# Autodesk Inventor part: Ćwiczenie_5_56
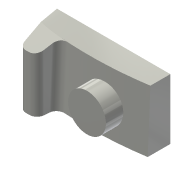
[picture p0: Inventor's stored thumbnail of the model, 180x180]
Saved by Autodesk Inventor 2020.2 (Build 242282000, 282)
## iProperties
Created: 2005-05
Part Number: Ćwiczenie_5_56
Document SubType Name: Modeling
Designer: F.Stasiak
Manufacturer: Standard
Standards Organization: Custom
Density: 1 g/cm^3
Material: Ogólny
Appearance: Gładkie — w kolorze kości słoniowej
Manager: www.cadconsulting.pl
Company: Fabian Stasiak CAD Consulting
Author: F.Stasiak
Subject: Zbiór ćwiczeń. Autodesk Inventor 2020. Kurs podstawowy
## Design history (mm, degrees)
sketch "Szkic1"
  geometry: L1 (-75, 0)-(75, 0); L2 (75, 0)-(75, -30); L3 (-75, 0)-(-75, -30); A1 r 496.531 centre (0, 460.834) between (-75, -30) and (75, -30); 2 further points
  constraints: 6 end point, 2 parallel, 2 point on circle, 1 centre point, 1 coincident, 1 horizontal, 1 midpoint, 1 perpendicular
  dimensions: "d0" = 150 distance of L1.start L1.end; "d1" = 30 distance of L1.end L2.end
extrude "Wyciągnięcie proste1" new body sketch "Szkic1" distance "d2" = 80; taper "d3" = 0 deg
feature "Szkic powierzchni1" dims angle "d4" = 2.5 deg
node "Płaszczyzna konstrukcyjna1"
sketch "Szkic6"
  geometry: C1 r 25 at (-19.767, 35.769)
  constraints: 1 centre point
  dimensions: "d14" = 50 diameter of C1
extrude "Wyciągnięcie proste3" join sketch "Szkic6" distance "d15" = 55; taper "d16" = 0 deg
sketch "Szkic14"
  geometry: L1 (0, 0)-(0, -80) reference; L2 (0, 0)-(35, 0); L3 (35, 0)-(35, -80); L4 (35, -80)-(0, -80); L5 (0, -80)-(0, 0)
  constraints: 8 end point, 2 parallel, 1 horizontal, 1 perpendicular
  dimensions: "d67" = 35 distance of L1.start L2.end
extrude "Wyciągnięcie proste4" join sketch "Szkic14" distance "d68" = 60; taper "d69" = 0 deg
sketch "Szkic16"
  geometry: L1 (80, 0)-(80, -60) reference; L2 (0, 0)-(80, 0) reference; L3 (0, 0)-(0, -60) reference; L4 (0, -60)-(80, -60) reference
extrude "Wyciągnięcie proste5" join sketch "Szkic16" distance "d85" = 9; taper "d86" = 0 deg
sketch "Szkic18"
  geometry: L1 (80, -60)-(0, -60) reference; L2 (80, 0)-(80, -60) reference; L3 (0, 0)-(80, 0) reference; L4 (0, -60)-(0, 0) reference
extrude "Wyciągnięcie proste6" cut sketch "Szkic18" distance "d116" = 9; taper "d117" = 0 deg
feature "Szkic powierzchni6" dims angle "d118" = 10 deg
feature "Szkic powierzchni7" dims angle "d119" = 5 deg
fillet "Zaokrąglenie2" dims "d120" = 10
sketch "Szkic20"
  geometry: L1 (-75, 0)-(-65.877, -51.736) reference; A1 r 493.038 centre (0, 460.834) between (-40, -30.579) and (75, -26.466) reference; A2 r 213.137 centre (-22.708, 181.855) between (-70.439, -25.868) and (-40, -30.579)
  constraints: 2 point on circle, 1 centre point, 1 midpoint, 1 tangent
feature "Podział8" sketch "Szkic20"
feature "Szkic powierzchni8" dims angle "d144" = 15 deg
fillet "Zaokrąglenie9" dims "d147" = 10
node "Płaszczyzna konstrukcyjna4"
node "Płaszczyzna konstrukcyjna5"
sketch "Szkic9"
  geometry: L1 (-75, 0)-(75, 0) reference; L2 (-40.884, -67.84)-(-37.231, -24.871); L3 (69.517, -25)-(80.483, -25); A1 r 16 centre (-55, -45) between (-70.121, -50.229) and (-39.057, -46.355); A2 r 182.693 centre (102.54, 9.477) between (-80, 2) and (-70.121, -50.229); A3 r 13.125 centre (75, -38.125) between (80.059, -26.014) and (69.941, -26.014); 7 further points
  constraints: 5 point on circle, 4 end point, 4 midpoint, 3 centre point, 2 horizontal, 2 tangent, 12 other
  dimensions: "d52" = 16 radius of A1; "d53" = 45 distance from line of L1 A1.centre; "d82" = 20 horizontal distance of L1.start A1.centre; "d83" = 5 horizontal distance of L1.start A2.start; "d84" = 2 vertical distance of L1.start A2.start; "d100" = 25 distance from line of L1 point (75, -25)
sketch "Szkic10"
  geometry: L1 (84, 0)-(-75, 0) reference; L2 (40.975, -68.914)-(37.14, -23.796); A1 r 16 centre (55, -45) between (39.057, -46.355) and (70.121, -50.229) reference; A2 r 182.693 centre (-102.54, 9.477) between (70.121, -50.229) and (80, 2) reference; A3 r 6574.736 centre (6590.17, 510.499) between (37.179, -23.793) and (41.014, -68.91); A4 r 16 centre (55, -45) between (39.057, -46.355) and (70.121, -50.229); A5 r 182.693 centre (-102.54, 9.477) between (70.121, -50.229) and (80, 2); 4 further points
  constraints: 5 point on circle, 3 centre point, 2 end point, 2 midpoint, 1 coincident, 1 concentric, 1 tangent, 7 other
  dimensions: "d101" = 15 distance from line of L1 point (-75, -15)
node "Oś konstrukcyjna2"
node "Płaszczyzna konstrukcyjna6"
node "Płaszczyzna konstrukcyjna7"
node "Płaszczyzna konstrukcyjna8"
node "Płaszczyzna konstrukcyjna9"
node "Punkt konstrukcyjny3"
node "Punkt konstrukcyjny4"
sketch "Szkic11"
  geometry: L1 (76.352, -18.919)-(103.648, -13.081); L2 (-11.256, -7.493)-(11.256, -24.507); A1 r 150 centre (45, 127.091) between (0, -16) and (90, -16); A2 r 22.217 centre (85.353, 5.725) between (77.731, -15.143) and (100.845, -10.199); A3 r 42.85 centre (25.836, 18.185) between (-9.396, -6.205) and (11.988, -22.365); 7 further points
  constraints: 7 point on circle, 4 end point, 4 midpoint, 3 centre point, 1 coincident, 12 other
  dimensions: "d56" = 150 radius of A1
sketch "Szkic12"
  geometry: A1 r 221.746 centre (217.132, 45) between (0, 90) and (0, 0)
  constraints: 2 point on circle, 1 centre point
sketch "Szkic13"
  geometry: A1 r 400 centre (-366.156, 45) between (31.305, 0) and (31.305, 90)
  constraints: 2 point on circle, 1 centre point
sketch "Szkic21"
  geometry: A1 r 97.956 centre (-3.074, -14.472) between (6.963, 82.968) and (-64.745, 61.633)
  constraints: 2 point on circle, 1 centre point
feature "Nowa powierzchnia górna" sketch "Szkic21" dims "d145" = 160, "d146" = 0
sketch "Szkic15"
  geometry: A1 r 448.447 centre (-446.183, -45) between (0, -90) and (0, 0)
  constraints: 2 point on circle, 1 centre point
sketch "Szkic17"
  geometry: L1 (-90.676, 5)-(-79.324, 5); A1 r 11.224 centre (-85, -6.224) between (-79.935, 3.792) and (-90.065, 3.792); 7 further points
  constraints: 2 end point, 2 horizontal, 2 midpoint, 1 centre point, 1 point on circle, 8 other
feature "Nowa powierzchnia czołowa" sketch "Szkic15", "Szkic17" dims "d125" = 0, "d126" = 90 deg, "d127" = 0, "d128" = 90 deg, "d129" = 0, "d130" = 90 deg, "d131" = 0, "d132" = 90 deg, "d133" = 0, "d134" = 90 deg, "d135" = 0, "d136" = 90 deg, "d137" = 0, "d138" = 90 deg
node "Bryła1"
node "Korpusy bryłowe"
node "Korpusy powierzchniowe"
body "Srf2"
body "Srf1"
other parameters: "d51" = 5, "d54" = 5, "d55" = 90 deg, "d122" = -85
